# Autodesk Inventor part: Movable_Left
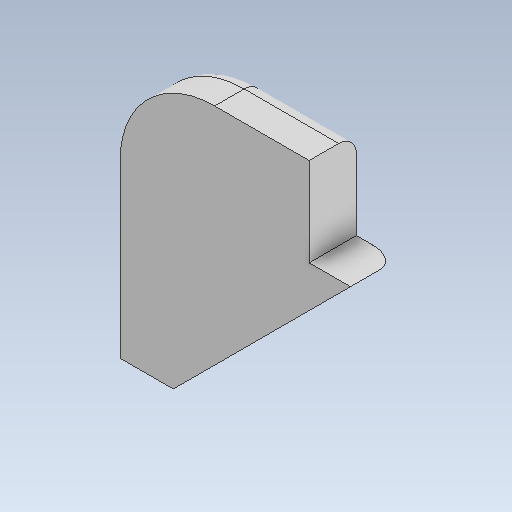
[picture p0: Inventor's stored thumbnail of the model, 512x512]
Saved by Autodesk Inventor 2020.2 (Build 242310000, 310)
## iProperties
Created: 2019-12
Part Number: Movable_Left
Material: Generic
Document SubType Name: Modeling
Designer: Patrick Everitt
Density: 1 g/cm^3
Appearance: Default
Description: 1x6 CRS 5 Lg
Author: Patrick Everitt
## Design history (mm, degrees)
sketch "Sketch1"
  geometry: L1 (-25.4, -3.175)-(-25.4, -50.8); L2 (-25.4, -50.8)-(-3.175, -50.8); L3 (-25.4, -3.175)-(-76.2, -3.175); L4 (-127, -53.975)-(-127, -146.05); L5 (-127, -146.05)-(-98.425, -146.05); L6 (-3.175, -50.8)-(-98.425, -146.05); A1 r 50.8 centre (-76.2, -53.975) between (-76.2, -3.175) and (-127, -53.975); 2 further points
  constraints: 12 end point, 3 horizontal, 2 point on circle, 2 point on line, 2 tangent, 2 vertical, 1 centre point
  dimensions: "d0" = 47.625 distance of L1.start L1.end; "d2" = 22.225 distance of L1.end L2.end; "d4" = 101.6 distance of L1.start point (-127, -3.175); "d6" = 142.875 distance of point (-127, -3.175) L4.end; "d9" = 45 deg angle of L6 L2; "d10" = 50.8 radius of A1
extrude "Extrusion1" new body sketch "Sketch1" distance "d11" = 25.4; taper "d12" = 0 deg
sketch "Sketch2"
  geometry: L1 (0, 0)-(0, 95.25) reference; L2 (0, 0)-(25.4, 0); L3 (25.4, 0)-(25.4, 92.075); L4 (0, 92.075)-(25.4, 92.075) reference; L5 (25.4, 88.9)-(9.525, 88.9); L6 (15.875, 0)-(15.875, 95.25) reference; L7 (0, 92.075)-(0, 0); A1 r 9.525 centre (9.525, 79.375) between (9.525, 88.9) and (0, 79.375); 5 further points
  constraints: 9 point on line, 8 end point, 3 perpendicular, 2 point on circle, 2 tangent, 1 centre point, 1 horizontal
  dimensions: "d23" = 25.4 vertical distance of L1.start point (16.662, 25.4) (= d24); "d24" = 25.4 distance from line of L5 point (16.662, 63.5); "d33" = 16.6624 distance from line of L1 point (16.662, 25.4); "d34" = 16.6624 distance from line of L1 point (16.662, 63.5) (= d33); "d35" = 88.9 distance from line of L1.start L5; "d37" = 9.525 radius of A1 (derived)
extrude "Extrusion2" join sketch "Sketch2" distance "d15" = 0.00025; taper "d16" = 0 deg
hole "Hole1" sketch "Sketch2" diameter "d25" = 6.4008; stored, may be unused: countersink angle "d29" = 82 deg, drill point angle "d31" = 118 deg; dims "d26" = 15.875, "d27" = 9.525, "d28" = 6.35, "d30" = 22.9362
fillet "Fillet6" dims "d38" = 9.525
fillet "Fillet7" dims "d39" = 9.525
fillet "Fillet8" dims "d40" = 3.175
body "Solid1"
other parameters: "d21" = 16.6624
